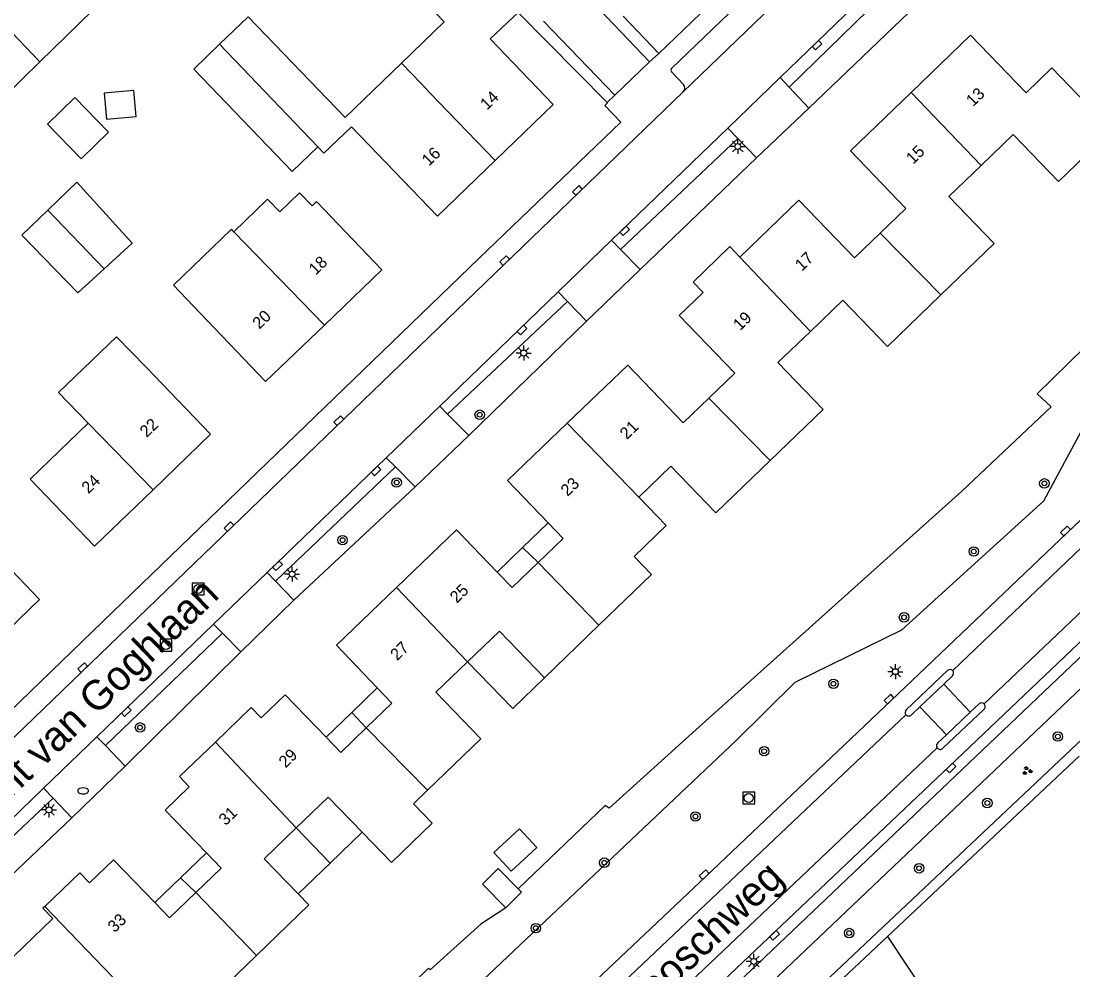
# Model space of a CAD drawing. Extents: x 136000 to 138005, y 398500 to 400500.
# Drawn here: x 137784.3 to 137872.8, y 399184 to 399263.7 of the extents above; entities that cross this region are included whole.
import ezdxf

# ---------------------------------------------------------------- set-up
doc = ezdxf.new("R2010")
doc.units = 0
for name, color, linetype in [('gg-afsc-erfafscheiding', 7, 'Continuous'), ('gg-anno-huisnummerreeks BGT', 7, 'Continuous'), ('gg-anno-openbare ruimte label', 7, 'Continuous'), ('gg-bbg-bijgebouw', 7, 'Continuous'), ('gg-bbg-gedigitaliseerde bebouwing', 7, 'Continuous'), ('gg-bbg-gedigitaliseerde bijgebouw', 7, 'Continuous'), ('gg-bbg-hoofdgebouw', 7, 'Continuous'), ('gg-bbg-luifel en loopbrug', 7, 'Continuous'), ('gg-bbg-tussenscheiding', 7, 'Continuous'), ('gg-knt-verharding', 7, 'Continuous'), ('gg-knt-verharding nz', 7, 'Continuous'), ('gt-grn-groengrens', 7, 'Continuous'), ('gt-symb-boom', 7, 'Continuous'), ('gt-symb-brandkraan', 7, 'Continuous'), ('gt-symb-groenvak', 7, 'Continuous'), ('gt-symb-kolk', 7, 'Continuous'), ('gt-symb-lichtmast', 7, 'Continuous'), ('gt-symb-rioolschacht', 7, 'Continuous')]:
    doc.layers.add(name, color=color, linetype=linetype)

# ---------------------------------------------------------------- blocks, each defined once
blk = doc.blocks.new('gt0-BOOM')
at = {"layer": 'gt-symb-boom'}
for radius in [0.4, 0.2]:
    blk.add_circle((0, 0), radius, dxfattribs=at)
blk = doc.blocks.new('gt0-KOLK')
at = {"layer": 'gt-symb-kolk'}
blk.add_lwpolyline([(0, 0), (0.375, 0), (0.375, 0.4), (-0.375, 0.4), (-0.375, 0), (0, 0)], dxfattribs=at)
blk = doc.blocks.new('gt0-GRVAK')
at = {"layer": 'gt-symb-groenvak'}
for p, q in [((-0.11, 0.189), (-0.228, 0.24)), ((-0.182, 0.153), (0.088, 0.153)), ((-0.091, 0.211), (-0.156, 0.322)), ((-0.047, 0.214), (-0.047, 0.393)), ((-0.004, 0.211), (0.061, 0.322)), ((0.015, 0.189), (0.133, 0.24)), ((0.262, -0.052), (0.197, 0.059)), ((0.305, -0.049), (0.305, 0.13)), ((0.349, -0.052), (0.414, 0.059)), ((-0.245, -0.228), (-0.363, -0.177)), ((-0.318, -0.264), (-0.047, -0.264)), ((-0.226, -0.206), (-0.291, -0.095)), ((-0.183, -0.203), (-0.183, -0.024)), ((-0.139, -0.206), (-0.074, -0.095)), ((-0.12, -0.228), (-0.002, -0.177)), ((0.243, -0.074), (0.125, -0.023)), ((0.17, -0.11), (0.441, -0.11)), ((0.368, -0.074), (0.486, -0.023))]:
    blk.add_line(p, q, dxfattribs=at)
blk = doc.blocks.new('gt0-LMAST')
at = {"layer": 'gt-symb-lichtmast'}
for p, q in [((-0.182, 0.173), (-0.447, 0.438)), ((-0.005, 0.246), (-0.005, 0.621)), ((0.172, 0.173), (0.437, 0.438)), ((-0.255, -0.004), (-0.63, -0.004)), ((-0.182, -0.181), (-0.447, -0.446)), ((-0.005, -0.254), (-0.005, -0.629)), ((0.437, -0.446), (0.172, -0.181)), ((0.245, -0.004), (0.62, -0.004))]:
    blk.add_line(p, q, dxfattribs=at)
blk.add_circle((-0.005, -0.004), 0.25, dxfattribs=at)
blk = doc.blocks.new('gt0-BR')
at = {"layer": 'gt-symb-brandkraan'}
for centre, radius, start, end in [((-0.244, 0), 0.206, 107.56694, 252.43307), ((0.599, -2.664), 3, 106.89205, 107.56694), ((0, -0.691), 0.938, 73.10799, 106.89205), ((-0.599, -2.664), 3, 72.43309, 73.10799), ((0.244, 0), 0.206, 287.56695, 72.43309), ((0.599, 2.664), 3, 252.43307, 253.10797), ((0, 0.691), 0.938, 253.10797, 286.89206), ((-0.599, 2.664), 3, 286.89206, 287.56695)]:
    blk.add_arc(centre, radius, start, end, dxfattribs=at)
blk = doc.blocks.new('gt0-RS')
at = {"layer": 'gt-symb-rioolschacht'}
blk.add_lwpolyline([(-0.5, -0.5), (0.5, -0.5), (0.5, 0.5), (-0.5, 0.5)], close=True, dxfattribs=at)
blk.add_circle((0, 0), 0.375, dxfattribs=at)

msp = doc.modelspace()

# ---------------------------------------------------------------- linework, layer by layer
at = {"layer": 'gg-afsc-erfafscheiding'}
for p, q in [((137826.103, 399264.465), (137833.592, 399256.898)), ((137837.928, 399261.011), (137837.156, 399260.313)), ((137873.3, 399201.92), (137857.171, 399186.764)), ((137857.171, 399186.764), (137865.836, 399173.781))]:
    msp.add_line(p, q, dxfattribs=at)
for points in [[(137897.333, 399259.365), (137869.772, 399232.394), (137870.947, 399231.295), (137863.403, 399224.196), (137841.052, 399204.139), (137833.761, 399197.544), (137833.432, 399197.769), (137826.11, 399190.778)], [(137825.075, 399189.184), (137822.962, 399187.802), (137818.701, 399183.952), (137818.574, 399184.116), (137813.558, 399179.202)], [(137857.171, 399186.764), (137844.473, 399174.83), (137844.891, 399174.091)]]:
    msp.add_lwpolyline(points, dxfattribs=at)
at = {"layer": 'gg-bbg-bijgebouw'}
for p in [(137828.232, 399263.742), (137837.156, 399260.313)]:
    msp.add_line(p, (137834.232, 399257.512), dxfattribs=at)
at = {"layer": 'gg-bbg-gedigitaliseerde bebouwing'}
for p, q in [((137837.928, 399261.011), (137834.94, 399264.142)), ((137816.288, 399260.21), (137819.892, 399263.684)), ((137809.774, 399252.622), (137809.248, 399253.168)), ((137809.15, 399248.569), (137808.773, 399248.207)), ((137814.65, 399242.83), (137809.15, 399248.569)), ((137802.182, 399246.029), (137801.99, 399246.228)), ((137799.36, 399239.179), (137804.86, 399233.44)), ((137800.24, 399229), (137794.811, 399234.632)), ((137785.85, 399215.11), (137780.357, 399220.808)), ((137828.319, 399208.515), (137832.9, 399212.936)), ((137817.302, 399197.93), (137818.485, 399199.072)), ((137812.978, 399195.54), (137813.869, 399194.617)), ((137799.509, 399180.759), (137804.09, 399185.18))]:
    msp.add_line(p, q, dxfattribs=at)
for points in [[(137819.892, 399263.684), (137816.314, 399267.398), (137817.715, 399268.748), (137813.145, 399273.493), (137815.328, 399275.595), (137820.913, 399269.854)], [(137785.883, 399260.314), (137790.325, 399264.642), (137788.099, 399266.927)], [(137816.288, 399260.21), (137811.55, 399255.643), (137803.396, 399264.102), (137800.988, 399261.783)], [(137779.233, 399258.133), (137781.382, 399255.928), (137785.883, 399260.314)], [(137865.047, 399251.582), (137867.749, 399254.189), (137871.564, 399250.236), (137876.038, 399254.554), (137871.01, 399259.8)], [(137861.667, 399240.71), (137866.149, 399245.034), (137862.346, 399248.975), (137865.047, 399251.582)], [(137808.773, 399248.207), (137807.726, 399249.295), (137806.068, 399247.701), (137805.035, 399248.774), (137802.182, 399246.029)], [(137801.99, 399246.228), (137797.105, 399241.519), (137799.36, 399239.179)], [(137850.684, 399237.646), (137853.405, 399240.272), (137857.17, 399236.37), (137861.667, 399240.71)], [(137847.299, 399226.79), (137851.755, 399231.09), (137847.963, 399235.02), (137850.684, 399237.646)], [(137794.811, 399234.632), (137792.333, 399237.202), (137787.453, 399232.498), (137789.931, 399229.927)], [(137789.931, 399229.927), (137785.051, 399225.222), (137790.48, 399219.59)], [(137836.253, 399223.706), (137838.943, 399226.301), (137842.728, 399222.379), (137847.299, 399226.79)], [(137835.864, 399218.727), (137838.553, 399221.323), (137836.253, 399223.706)], [(137832.9, 399212.936), (137837.329, 399217.209), (137835.864, 399218.727)], [(137821.856, 399209.873), (137824.524, 399212.448), (137828.319, 399208.515)], [(137818.485, 399199.072), (137822.96, 399203.39), (137819.188, 399207.299), (137821.856, 399209.873)], [(137807.437, 399195.897), (137810.128, 399198.494), (137812.978, 399195.54)], [(137813.869, 399194.617), (137815.446, 399192.983), (137818.879, 399196.295), (137817.302, 399197.93)], [(137807.596, 399190.347), (137804.746, 399193.301), (137807.437, 399195.897)], [(137804.09, 399185.18), (137808.487, 399189.423), (137807.596, 399190.347)]]:
    msp.add_lwpolyline(points, dxfattribs=at)
at = {"layer": 'gg-bbg-gedigitaliseerde bijgebouw'}
for p, q in [((137834.181, 399263.418), (137831.172, 399266.559)), ((137837.156, 399260.313), (137834.181, 399263.418))]:
    msp.add_line(p, q, dxfattribs=at)
for points in [[(137809.248, 399253.168), (137807.094, 399251.095), (137798.819, 399259.695), (137800.988, 399261.783)], [(137791.49, 399255.488), (137793.971, 399255.721), (137793.766, 399257.9), (137791.286, 399257.667), (137791.49, 399255.488)], [(137786.543, 399247.842), (137788.972, 399250.184), (137793.641, 399245.059), (137791.285, 399242.913)], [(137791.285, 399242.913), (137789.055, 399240.881), (137784.367, 399245.745), (137786.543, 399247.842)], [(137826.215, 399195.82), (137824.061, 399193.839), (137825.514, 399192.258), (137827.669, 399194.239), (137826.215, 399195.82)], [(137826.11, 399190.778), (137824.424, 399192.472), (137823.107, 399191.162), (137825.075, 399189.184)], [(137825.075, 399189.184), (137826.392, 399190.495), (137826.11, 399190.778)]]:
    msp.add_lwpolyline(points, dxfattribs=at)
at = {"layer": 'gg-bbg-hoofdgebouw'}
for p, q in [((137849.034, 399271.674), (137837.928, 399261.011)), ((137824.185, 399252.015), (137829.06, 399256.71)), ((137819.317, 399247.326), (137824.185, 399252.015)), ((137814.65, 399242.83), (137809.803, 399238.181)), ((137809.803, 399238.181), (137804.86, 399233.44)), ((137800.24, 399229), (137795.393, 399224.326)), ((137795.393, 399224.326), (137790.48, 399219.59)), ((137785.85, 399215.11), (137781.016, 399210.454))]:
    msp.add_line(p, q, dxfattribs=at)
for points in [[(137829.06, 399256.71), (137823.739, 399262.235), (137826.103, 399264.465)], [(137871.01, 399259.8), (137868.83, 399257.71), (137864.17, 399262.55), (137859.153, 399257.727)], [(137859.153, 399257.727), (137854.07, 399252.84), (137858.73, 399247.99), (137856.56, 399245.905)], [(137809.774, 399252.622), (137812.078, 399254.849), (137819.317, 399247.326)], [(137856.56, 399245.905), (137854.39, 399243.82), (137849.73, 399248.67), (137844.766, 399243.897)], [(137841.658, 399240.91), (137840.817, 399241.793), (137843.92, 399244.776), (137844.766, 399243.897)], [(137841.658, 399240.91), (137839.65, 399238.98), (137844.32, 399234.13), (137842.152, 399232.042)], [(137842.152, 399232.042), (137839.99, 399229.96), (137835.32, 399234.81), (137830.231, 399229.927)], [(137830.231, 399229.927), (137825.21, 399225.11), (137828.626, 399221.54)], [(137828.626, 399221.54), (137829.88, 399220.23), (137827.792, 399218.215)], [(137824.342, 399217.406), (137820.92, 399220.96), (137815.878, 399216.108)], [(137827.792, 399218.215), (137825.6, 399216.1), (137824.342, 399217.406)], [(137815.878, 399216.108), (137810.83, 399211.25), (137814.261, 399207.679)], [(137814.261, 399207.679), (137815.49, 399206.4), (137813.335, 399204.325)], [(137809.954, 399203.523), (137806.51, 399207.1), (137804.491, 399205.159)], [(137800.637, 399203.12), (137803.659, 399206.024), (137804.491, 399205.159)], [(137813.335, 399204.325), (137811.18, 399202.25), (137809.954, 399203.523)], [(137798.439, 399199.341), (137797.607, 399200.207), (137800.637, 399203.12)], [(137798.439, 399199.341), (137796.42, 399197.4), (137799.883, 399193.805)], [(137795.542, 399189.616), (137792.08, 399193.21), (137790.062, 399191.268)], [(137799.883, 399193.805), (137801.12, 399192.52), (137798.989, 399190.463)], [(137790.062, 399191.268), (137789.229, 399192.133), (137786.289, 399189.303)], [(137798.989, 399190.463), (137796.78, 399188.33), (137795.542, 399189.616)], [(137786.289, 399189.303), (137786.13, 399189.15), (137786.962, 399188.285)], [(137786.962, 399188.285), (137782.01, 399183.52), (137786.69, 399178.68), (137784.569, 399176.628)]]:
    msp.add_lwpolyline(points, dxfattribs=at)
at = {"layer": 'gg-bbg-luifel en loopbrug'}
for p, q in [((137826.484, 399219.473), (137828.626, 399221.54)), ((137824.342, 399217.406), (137826.484, 399219.473)), ((137827.792, 399218.215), (137826.484, 399219.473)), ((137812.108, 399205.601), (137814.261, 399207.679)), ((137809.954, 399203.523), (137812.108, 399205.601)), ((137813.335, 399204.325), (137812.108, 399205.601)), ((137807.437, 399195.897), (137810.287, 399192.944)), ((137810.287, 399192.944), (137812.978, 399195.54)), ((137799.883, 399193.805), (137797.712, 399191.71)), ((137807.596, 399190.347), (137810.287, 399192.944)), ((137797.712, 399191.71), (137795.542, 399189.616)), ((137798.989, 399190.463), (137797.712, 399191.71))]:
    msp.add_line(p, q, dxfattribs=at)
for points in [[(137789.341, 399252.153), (137786.508, 399255.069), (137788.807, 399257.303), (137791.64, 399254.387), (137789.341, 399252.153)], [(137828.319, 399208.515), (137825.651, 399205.94), (137821.856, 399209.873)]]:
    msp.add_lwpolyline(points, dxfattribs=at)
at = {"layer": 'gg-bbg-tussenscheiding'}
for p, q in [((137780.86, 399265.484), (137785.883, 399260.314)), ((137800.988, 399261.783), (137809.248, 399253.168)), ((137818.663, 399257.743), (137824.185, 399252.015)), ((137859.153, 399257.727), (137865.047, 399251.582)), ((137786.543, 399247.842), (137791.285, 399242.913)), ((137802.182, 399246.029), (137809.803, 399238.181)), ((137856.56, 399245.905), (137861.667, 399240.71)), ((137844.766, 399243.897), (137850.684, 399237.646)), ((137842.152, 399232.042), (137847.299, 399226.79)), ((137789.931, 399229.927), (137795.393, 399224.326)), ((137830.231, 399229.927), (137836.253, 399223.706)), ((137827.792, 399218.215), (137832.9, 399212.936)), ((137815.878, 399216.108), (137821.856, 399209.873)), ((137813.335, 399204.325), (137818.485, 399199.072)), ((137800.637, 399203.12), (137807.437, 399195.897)), ((137798.989, 399190.463), (137804.09, 399185.18)), ((137786.289, 399189.303), (137795.296, 399179.96))]:
    msp.add_line(p, q, dxfattribs=at)
msp.add_lwpolyline([(137818.663, 399257.743), (137817.918, 399258.519), (137816.288, 399260.21)], dxfattribs=at)
at = {"layer": 'gg-knt-verharding'}
for p, q in [((137855.641, 399275.752), (137839.016, 399259.763)), ((137858.197, 399268.697), (137848.145, 399258.998)), ((137839.002, 399259.478), (137840.009, 399258.409)), ((137848.145, 399258.998), (137843.733, 399254.741)), ((137848.145, 399258.998), (137848.915, 399258.18)), ((137848.915, 399258.18), (137850.564, 399256.429)), ((137834.232, 399257.512), (137833.592, 399256.898)), ((137850.564, 399256.429), (137846.168, 399252.233)), ((137843.733, 399254.741), (137833.963, 399245.314)), ((137844.583, 399253.866), (137843.733, 399254.741)), ((137846.168, 399252.233), (137844.583, 399253.866)), ((137865.304, 399206.317), (137908.236, 399247.172)), ((137833.963, 399245.314), (137829.466, 399240.974)), ((137834.726, 399244.532), (137833.963, 399245.314)), ((137836.373, 399242.847), (137834.726, 399244.532)), ((137836.373, 399242.847), (137831.861, 399238.496)), ((137862.659, 399209.127), (137898.279, 399243.232)), ((137830.266, 399240.147), (137829.466, 399240.974)), ((137831.861, 399238.496), (137830.266, 399240.147)), ((137814.999, 399227.017), (137819.506, 399231.361)), ((137819.506, 399231.361), (137820.175, 399230.688)), ((137820.175, 399230.688), (137821.954, 399228.897)), ((137817.45, 399224.588), (137821.954, 399228.897)), ((137804.987, 399217.366), (137814.999, 399227.017)), ((137814.999, 399227.017), (137815.777, 399226.246)), ((137815.777, 399226.246), (137817.45, 399224.588)), ((137800.494, 399213.036), (137804.987, 399217.366)), ((137804.987, 399217.366), (137805.694, 399216.64)), ((137805.694, 399216.64), (137807.251, 399215.04)), ((137807.251, 399215.04), (137802.77, 399210.696)), ((137790.669, 399203.566), (137800.494, 399213.036)), ((137800.494, 399213.036), (137801.247, 399212.261)), ((137801.247, 399212.261), (137802.77, 399210.696)), ((137858.756, 399205.836), (137862.235, 399209.125)), ((137861.913, 399207.985), (137862.639, 399208.676)), ((137859.895, 399206.087), (137861.913, 399207.985)), ((137861.913, 399207.985), (137864.126, 399205.616)), ((137864.126, 399205.616), (137864.882, 399206.322)), ((137825.276, 399173.764), (137858.728, 399205.413)), ((137859.18, 399205.407), (137859.895, 399206.087)), ((137859.895, 399206.087), (137862.125, 399203.728)), ((137861.827, 399202.593), (137865.291, 399205.862)), ((137862.125, 399203.728), (137864.126, 399205.616)), ((137861.414, 399203.041), (137862.125, 399203.728)), ((137786.185, 399199.248), (137790.669, 399203.566)), ((137790.669, 399203.566), (137791.384, 399202.819)), ((137791.384, 399202.819), (137793.048, 399201.078)), ((137827.925, 399170.96), (137861.357, 399202.62)), ((137788.56, 399196.746), (137793.048, 399201.078)), ((137776.308, 399189.736), (137786.185, 399199.248)), ((137786.985, 399198.405), (137786.185, 399199.248)), ((137788.56, 399196.746), (137786.985, 399198.405))]:
    msp.add_line(p, q, dxfattribs=at)
for points in [[(137839.995, 399257.78), (137833.565, 399251.602), (137798.869, 399218.145), (137747.243, 399168.384), (137746.5, 399167.669)], [(137833.592, 399256.898), (137833.629, 399256.861), (137833.401, 399256.634), (137834.753, 399255.227), (137822.788, 399243.788), (137792.019, 399214.064), (137777.226, 399199.803), (137773.358, 399196.11)], [(137909.468, 399245.877), (137905.437, 399242.026), (137891.309, 399228.607), (137877.226, 399215.18), (137862.388, 399201.082), (137831.931, 399172.217), (137830.741, 399171.113)], [(137829.466, 399240.974), (137820.358, 399232.182), (137819.506, 399231.361)], [(137824.096, 399175.014), (137827.002, 399177.752), (137841.886, 399191.825), (137857.448, 399206.588), (137872.288, 399220.717), (137886.399, 399234.106), (137891.621, 399239.108)], [(137830.741, 399171.113), (137832.273, 399169.448), (137837.149, 399175.748), (137837.709, 399176.351), (137900.667, 399236.166)], [(137835.205, 399170.035), (137838.923, 399174.815), (137901.976, 399234.759)]]:
    msp.add_lwpolyline(points, dxfattribs=at)
for centre, radius, start, end in [((137839.206, 399259.611), 0.244, 141.36029, 213.01517), ((137839.68, 399258.102), 0.45, 314.4119, 43.038), ((137862.448, 399208.918), 0.297, 44.71309, 135.82744), ((137862.411, 399208.912), 0.328, 313.9731, 40.94856), ((137865.09, 399206.087), 0.314, 47.07588, 131.56647), ((137865.081, 399206.096), 0.314, 311.98074, 44.7461), ((137858.977, 399205.609), 0.317, 134.26494, 218.16085), ((137858.956, 399205.59), 0.289, 217.72479, 320.75417), ((137861.605, 399202.801), 0.307, 128.54226, 216.03674), ((137861.604, 399202.809), 0.311, 217.47866, 315.94565)]:
    msp.add_arc(centre, radius, start, end, dxfattribs=at)
at = {"layer": 'gg-knt-verharding nz'}
msp.add_line((137857.543, 399274.724), (137839.995, 399257.78), dxfattribs=at)
at = {"layer": 'gt-grn-groengrens'}
for p, q in [((137858.908, 399267.935), (137848.915, 399258.18)), ((137860.646, 399266.071), (137850.564, 399256.429)), ((137844.583, 399253.866), (137834.726, 399244.532)), ((137846.168, 399252.233), (137836.373, 399242.847)), ((137830.266, 399240.147), (137820.175, 399230.688)), ((137831.861, 399238.496), (137821.954, 399228.897)), ((137815.777, 399226.246), (137805.694, 399216.64)), ((137817.45, 399224.588), (137807.251, 399215.04)), ((137801.247, 399212.261), (137791.384, 399202.819)), ((137802.77, 399210.696), (137793.048, 399201.078)), ((137786.985, 399198.405), (137777.024, 399188.984)), ((137788.56, 399196.746), (137778.607, 399187.322))]:
    msp.add_line(p, q, dxfattribs=at)
for points in [[(137776.3, 399143.93), (137788.755, 399150.918), (137792.628, 399152.632), (137801.605, 399160.403), (137813.8, 399174.28), (137844.456, 399203.247), (137849.411, 399208.152), (137858.387, 399212.562), (137870.313, 399223.401), (137874.061, 399230.312), (137873.577, 399232.042), (137876.755, 399234.461), (137881.221, 399239.237), (137891.181, 399248.434), (137901.583, 399257.529), (137910.029, 399265.853)], [(137911.091, 399238.043), (137910.725, 399238.433), (137837.977, 399169.819), (137839.071, 399168.686), (137844.439, 399173.671)]]:
    msp.add_lwpolyline(points, dxfattribs=at)

# ---------------------------------------------------------------- block references
at = {"layer": 'gt-symb-boom'}
for p in [(137822.876, 399230.639), (137815.884, 399224.939), (137870.37, 399224.866), (137811.335, 399220.093), (137864.433, 399219.144), (137858.568, 399213.604), (137852.63, 399208.017), (137794.303, 399204.349), (137871.502, 399203.578), (137846.802, 399202.347), (137865.569, 399197.993), (137841.022, 399196.856), (137833.355, 399192.972), (137859.832, 399192.503), (137827.593, 399187.468), (137853.95, 399187.056)]:
    msp.add_blockref('gt0-BOOM', p, dxfattribs=at)
at = {"layer": 'gt-symb-brandkraan'}
msp.add_blockref('gt0-BR', (137789.513, 399199.013), dxfattribs=at)
at = {"layer": 'gt-symb-groenvak'}
msp.add_blockref('gt0-GRVAK', (137868.911, 399200.696), dxfattribs=at)
at = {"layer": 'gt-symb-kolk'}
for p, rotation in [((137851.107, 399261.856), -136.02150192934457), ((137831.235, 399249.354), 43.955676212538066), ((137834.929, 399246.246), -136.0215019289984), ((137825.118, 399243.456), 43.955676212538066), ((137826.29, 399237.908), -136.01569525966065), ((137811.161, 399229.998), 43.95567621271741), ((137814.002, 399226.056), -136.05573459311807), ((137801.918, 399221.085), 43.95567621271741), ((137872.288, 399220.717), 43.499019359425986), ((137805.726, 399218.079), -136.05573459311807), ((137789.624, 399209.234), 43.94426540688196), ((137857.448, 399206.588), 43.59614055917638), ((137792.999, 399205.812), -136.05573459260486), ((137862.388, 399201.082), -135.65618230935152), ((137841.886, 399191.825), 43.493464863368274), ((137847.537, 399187.007), -136.53520734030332)]:
    msp.add_blockref('gt0-KOLK', p, dxfattribs=dict(at, rotation=rotation))
at = {"layer": 'gt-symb-lichtmast'}
for p in [(137844.589, 399253.191), (137826.58, 399235.828), (137807.095, 399217.24), (137857.839, 399209.039), (137786.644, 399197.415), (137845.929, 399184.676)]:
    msp.add_blockref('gt0-LMAST', p, dxfattribs=at)
at = {"layer": 'gt-symb-rioolschacht'}
for p in [(137799.19, 399215.983), (137796.487, 399211.271), (137845.504, 399198.413)]:
    msp.add_blockref('gt0-RS', p, dxfattribs=at)

# ---------------------------------------------------------------- texts
at = {"layer": 'gg-anno-huisnummerreeks BGT'}
for s, rotation, p in [('14', 43.9, (137823.49, 399256.206)), ('13', 43.9, (137864.364, 399256.494)), ('16', 43.9, (137818.589, 399251.485)), ('15', 43.9, (137859.314, 399251.639)), ('17', 43.9, (137849.975, 399242.663)), ('18', 43.8, (137809.072, 399242.33)), ('20', 43.8, (137804.335, 399237.786)), ('19', 43.9, (137844.766, 399237.656)), ('22', 43.9, (137794.864, 399228.679)), ('21', 43.8, (137835.24, 399228.497)), ('24', 43.9, (137789.96, 399223.951)), ('23', 43.8, (137830.261, 399223.72)), ('25', 43.9, (137820.945, 399214.739)), ('27', 43.9, (137815.929, 399209.913)), ('29', 43.9, (137806.545, 399200.891)), ('31', 43.9, (137801.499, 399196.04)), ('33', 43.9, (137792.162, 399187.043))]:
    msp.add_text(s, height=1, rotation=rotation, dxfattribs=at).set_placement(p)
at = {"layer": 'gg-anno-openbare ruimte label'}
for s, rotation, p in [('Vincent van Goghlaan', 43.9, (137777.384, 399192.536)), ('Eikenboschweg', 43.5, (137831.617, 399175.395))]:
    msp.add_text(s, height=2.5, rotation=rotation, dxfattribs=at).set_placement(p)

doc.saveas('drawing.dxf')
